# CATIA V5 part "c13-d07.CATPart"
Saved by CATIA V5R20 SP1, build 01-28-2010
Part number: Part1
Bounding box of the stored display mesh (mm): x -49.812 to 35, y -44.222 to 44.222, z 0 to 30
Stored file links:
  D:\v5_r20\psrt_files_downloaded\c13-catia-v5r20-prt\c13-catia-v5r20-figr-13-24 & 25\c13-d07.CATPart
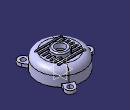
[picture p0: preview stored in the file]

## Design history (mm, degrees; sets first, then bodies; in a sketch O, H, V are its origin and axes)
Body1 (main body)
  Sketch1 on yz-plane, origin (0, 0, 0), H (0, 1, 0), V (0, 0, 1)
    line L1 (0, 0) -> (35, 0)
    line L2 (35, 0) -> (35, 15)
    arc A1 centre (25, 15) radius 10 from (35, 15) to (25, 25) ccw
    line L3 (25, 25) -> (0, 25)
    point P5 (0, 25)
    line L4 (0, 25) -> (0, 0)
    axis line L5 (0, 70.1891) -> (0, -36.6898)
    point P6 (0, 70.1891)
    "Radius" L2 L5 = 35
    distance L1 L3 = 25
    radius A1 = 10
    horizontal: L1 H
    vertical: L2 V, L4 V, L5 V
    tangency: A1 L2, L3 A1
    coincidence: P5 V, P6 V
  Shaft1: profile Sketch1, axis Sketch1.L5, angle 360
  Shell1: IntOffset 2.5, Face face of Shaft1, ExtOffset 0
  Sketch2 on face of Shaft1, origin (0, 0, 0), H (1, 0, 0), V (0, -1, 0)
    projected circle E1 centre (0, 0) radius 35 from edge [face of Shaft1 | face of Shaft1]
    projected arc E2 centre (0, 0) radius 35 from (-34.187, 7.5) to (-34.187, -7.5) ccw from edge [face of Shaft1 | face of Shaft1]
    point P1 (-34.187, 7.5)
    line L1 (-34.187, 7.5) -> (-42.5, 7.5)
    arc A1 centre (-42.5, 0) radius 7.5 from (-42.5, 7.5) to (-42.5, -7.5) ccw
    point P3 (-42.5, 0)
    line L2 (-42.5, -7.5) -> (-34.187, -7.5)
    point P5 (-34.187, -7.5)
    circle A2 centre (-42.5, 0) radius 3.75
    distance P3 V = 42.5
    radius A1 = 7.5
    radius A2 = 3.75
    coincidence: P1 E1, P5 E1, P3 H
    horizontal: L1 H, L2 H
    tangency: A1 L1, L2 A1
  Pad1: profile Sketch2, direction (0, 0, 1), length 5
  CircPattern1: of Pad1, instances 3, angular step 120 {= 360.0*1 deg/CircPattern1.AngularNumber}, axis from face of Shaft1
  Sketch3 on face of Shaft1, origin (0, 0, 25), H (1, 0, 0), V (0, 1, 0)
    construction line L1 (-20, -18) -> (20, -18)
    point P2 (20, -18)
    line L2 (-20, -16.25) -> (20, -16.25)
    line L3 (20, -19.75) -> (-20, -19.75)
    arc A1 centre (20, -18) radius 1.75 from (20, -16.25) to (20, -19.75) cw
    arc A2 centre (-20, -18) radius 1.75 from (-20, -19.75) to (-20, -16.25) cw
    length L1 = 40
    distance H L1 = 18
    distance P2 V = 20
    distance L3 L2 = 3.5
    horizontal: L1 H
    tangency: A1 L2, A2 L2, A1 L3, A2 L3
    parallelism: L1 L2
  Pocket1: profile Sketch3, direction (0, 0, -1), through (limit type 3)
  RectPattern1: of Pocket1, direction 1 instances 7, spacing 6, along yz-plane
  Sketch4 on yz-plane, origin (0, 0, 0), H (0, 1, 0), V (0, 0, 1)
    axis line L1 (0, 0) -> (0, 35.5018)
    point P2 (0, 22.5)
    line L2 (0, 22.5) -> (12.5, 22.5)
    line L3 (12.5, 22.5) -> (12.5, 28)
    arc A1 centre (10.5, 28) radius 2 from (12.5, 28) to (10.5, 30) ccw
    line L4 (10.5, 30) -> (0, 30)
    point P7 (0, 30)
    line L5 (0, 30) -> (0, 22.5)
    reference intersected line E1 (25, 22.5) -> (-25, 22.5) from face of Shell1
    "Radius" L3 L1 = 12.5
    distance L4 L2 = 7.5
    radius A1 = 2
    vertical: L1 V, L3 V, L5 V
    coincidence: P2 L1, P7 L1, L2 E1
    horizontal: L2 H, L4 H
    tangency: A1 L3, L4 A1
  Shaft2: profile Sketch4, axis Sketch4.L1, angle 360
  Sketch5 on face of Shaft2, origin (0, 0, 30), H (1, 0, 0), V (0, 1, 0)
    point P1 (0, 0)
    reference projected circle E1 centre (0, 0) radius 12.5 from edge [face of Shaft2 | face of Shaft2]
    concentricity: P1 E1
  Hole1: placed by Sketch5, at (0, 0, 30) direction (0, 0, -1), diameter 15, through (limit type 3)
